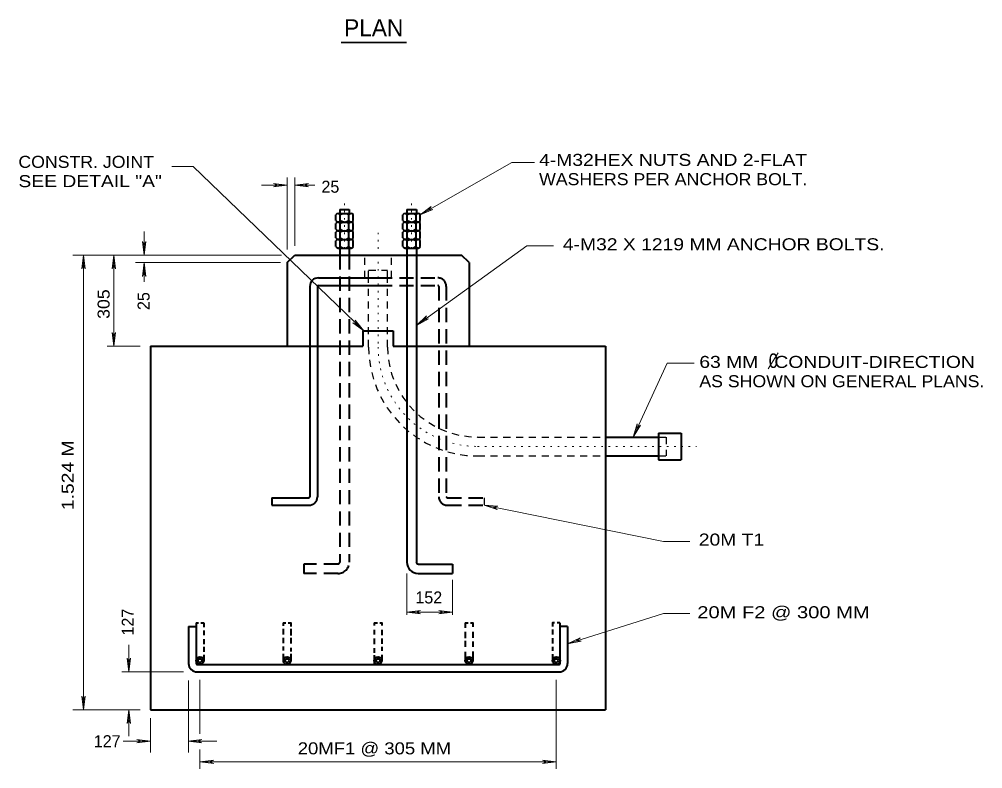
# Model space of a CAD drawing. Extents: x 312583 to 312854, y 144419 to 144597.
# Drawn here: x 312735.4 to 312796.3, y 144490 to 144537.4 of the extents above; entities that cross this region are included whole.
import ezdxf
from ezdxf.enums import TextEntityAlignment as Align

# ---------------------------------------------------------------- set-up
doc = ezdxf.new("R2010")
doc.units = 0
doc.header["$LTSCALE"] = 0.3
for name, pattern in [('DOTTED', [1.5, 0.3, -1.2]), ('MEDIUM_DASHED', [4.5, 3, -1.5]), ('SHORT_DASHED', [2.7, 1.5, -1.2])]:
    doc.linetypes.add(name, pattern=pattern)
doc.layers.add('1', color=7, linetype='Continuous', lineweight=40)
doc.layers.add('2', color=7, linetype='Continuous', lineweight=13)

msp = doc.modelspace()

# ---------------------------------------------------------------- linework, layer by layer
at = {"layer": '1', "linetype": 'DOTTED', "lineweight": 13}
for p, q in [((312755.9183, 144525.7646), (312755.9183, 144522.1076)), ((312760.158, 144525.7646), (312760.158, 144522.1076)), ((312758.0343, 144523.9169), (312758.0343, 144516.6873)), ((312764.3286, 144510.4006), (312778.167, 144510.4006))]:
    msp.add_line(p, q, dxfattribs=at)
at = {"layer": '1'}
for p, q in [((312755.374, 144524.6836), (312755.374, 144525.0516)), ((312755.512, 144525.1359), (312756.34, 144525.1359)), ((312755.6193, 144525.3736), (312756.2173, 144525.3736)), ((312755.6193, 144525.3736), (312755.6193, 144525.1359)), ((312755.65, 144524.6836), (312755.65, 144525.0516)), ((312756.1943, 144524.6836), (312756.1943, 144525.0516)), ((312756.2173, 144525.3736), (312756.2173, 144525.1359)), ((312756.4703, 144524.6836), (312756.4703, 144525.0516)), ((312759.606, 144524.6836), (312759.606, 144525.0516)), ((312759.744, 144525.1359), (312760.572, 144525.1359)), ((312759.859, 144525.3736), (312760.457, 144525.3736)), ((312759.859, 144525.3736), (312759.859, 144525.1359)), ((312759.882, 144524.6836), (312759.882, 144525.0516)), ((312760.434, 144524.6836), (312760.434, 144525.0516)), ((312760.457, 144525.3736), (312760.457, 144525.1359)), ((312760.7023, 144524.6836), (312760.7023, 144525.0516)), ((312755.374, 144524.1316), (312755.374, 144524.4996)), ((312755.512, 144524.5916), (312756.34, 144524.5916)), ((312755.512, 144524.5916), (312756.34, 144524.5916)), ((312755.65, 144524.1316), (312755.65, 144524.4996)), ((312756.1943, 144524.1316), (312756.1943, 144524.4996)), ((312756.4703, 144524.1316), (312756.4703, 144524.4996)), ((312759.606, 144524.1316), (312759.606, 144524.4996)), ((312759.744, 144524.5916), (312760.572, 144524.5916)), ((312759.744, 144524.5916), (312760.572, 144524.5916)), ((312759.882, 144524.1316), (312759.882, 144524.4996)), ((312760.434, 144524.1316), (312760.434, 144524.4996)), ((312760.7023, 144524.1316), (312760.7023, 144524.4996)), ((312755.374, 144523.5873), (312755.374, 144523.9553)), ((312755.512, 144524.0396), (312756.34, 144524.0396)), ((312755.65, 144523.5873), (312755.65, 144523.9553)), ((312756.1943, 144523.5873), (312756.1943, 144523.9553)), ((312756.4703, 144523.5873), (312756.4703, 144523.9553)), ((312759.606, 144523.5873), (312759.606, 144523.9553)), ((312759.744, 144524.0396), (312760.572, 144524.0396)), ((312759.882, 144523.5873), (312759.882, 144523.9553)), ((312760.434, 144523.5873), (312760.434, 144523.9553)), ((312760.7023, 144523.5873), (312760.7023, 144523.9553)), ((312755.374, 144523.0353), (312755.374, 144523.4033)), ((312755.512, 144523.4953), (312756.34, 144523.4953)), ((312755.65, 144523.0353), (312755.65, 144523.4033)), ((312756.1943, 144523.0353), (312756.1943, 144523.4033)), ((312756.4703, 144523.0353), (312756.4703, 144523.4033)), ((312759.606, 144523.0353), (312759.606, 144523.4033)), ((312759.744, 144523.4953), (312760.572, 144523.4953)), ((312759.882, 144523.0353), (312759.882, 144523.4033)), ((312760.434, 144523.0353), (312760.434, 144523.4033)), ((312760.7023, 144523.0353), (312760.7023, 144523.4033)), ((312755.512, 144522.9433), (312756.34, 144522.9433)), ((312755.6193, 144522.9433), (312755.6193, 144522.4986)), ((312756.2173, 144522.9433), (312756.2173, 144522.4986)), ((312759.744, 144522.9433), (312760.572, 144522.9433)), ((312759.859, 144522.9433), (312759.859, 144503.0943)), ((312760.457, 144522.9433), (312760.457, 144503.0943)), ((312752.2843, 144522.0233), (312752.7673, 144522.4986)), ((312752.2843, 144522.0233), (312752.2843, 144516.7486)), ((312752.7673, 144522.4986), (312763.309, 144522.4986)), ((312763.7843, 144522.0233), (312763.309, 144522.4986)), ((312763.7843, 144522.0233), (312763.7843, 144516.7486)), ((312754.2623, 144521.0649), (312758.0343, 144521.0649)), ((312753.7256, 144520.5206), (312753.7256, 144507.2266)), ((312754.201, 144520.5206), (312754.201, 144507.2266)), ((312754.2623, 144520.5819), (312758.0343, 144520.5819)), ((312757.076, 144517.7069), (312758.9926, 144517.7069)), ((312757.076, 144517.7069), (312757.076, 144516.7486)), ((312758.9926, 144517.7069), (312758.9926, 144516.7486)), ((312743.6593, 144516.7486), (312743.6593, 144493.7486)), ((312743.6593, 144516.7486), (312757.076, 144516.7486)), ((312758.9926, 144516.7486), (312772.4093, 144516.7486)), ((312772.4093, 144516.7486), (312772.4093, 144493.7486)), ((312772.4093, 144510.9986), (312775.7673, 144510.9986)), ((312775.7673, 144511.2363), (312775.7673, 144509.5649)), ((312775.7673, 144511.2363), (312777.201, 144511.2363)), ((312777.201, 144511.2363), (312777.201, 144509.5649)), ((312772.4093, 144509.8026), (312775.7673, 144509.8026)), ((312775.7673, 144509.5649), (312777.201, 144509.5649)), ((312751.326, 144507.1653), (312753.6643, 144507.1653)), ((312751.326, 144507.1653), (312751.326, 144506.6899)), ((312751.326, 144506.6899), (312753.6643, 144506.6899)), ((312760.572, 144502.9716), (312762.734, 144502.9716)), ((312762.734, 144502.9716), (312762.734, 144502.3736)), ((312760.572, 144502.3736), (312762.734, 144502.3736)), ((312746.059, 144499.0233), (312746.059, 144496.6849)), ((312746.059, 144499.0233), (312746.5343, 144499.0233)), ((312746.5343, 144499.2609), (312746.5343, 144496.6849)), ((312746.5343, 144499.2609), (312746.6953, 144499.2609)), ((312746.841, 144499.2609), (312747.0173, 144499.2609)), ((312747.0173, 144499.2609), (312747.0173, 144498.9696)), ((312752.0466, 144499.2609), (312752.0466, 144499.0539)), ((312752.0466, 144499.2609), (312752.2, 144499.2609)), ((312752.0466, 144498.8699), (312752.0466, 144498.5096)), ((312752.5296, 144498.8699), (312752.5296, 144498.4483)), ((312757.7966, 144499.2609), (312757.7966, 144499.0923)), ((312757.7966, 144499.2609), (312757.996, 144499.2609)), ((312757.7966, 144498.8009), (312757.7966, 144498.5096)), ((312758.2796, 144498.8009), (312758.2796, 144498.4713)), ((312763.5466, 144499.2609), (312763.723, 144499.2609)), ((312763.5466, 144499.2609), (312763.5466, 144498.9313)), ((312769.059, 144498.8239), (312769.059, 144498.5096)), ((312769.5343, 144499.2609), (312769.3503, 144499.2609)), ((312769.5343, 144499.2609), (312769.5343, 144496.6849)), ((312770.0173, 144499.0233), (312769.5343, 144499.0233)), ((312770.0173, 144499.0233), (312770.0173, 144496.6849)), ((312747.0173, 144498.7626), (312747.0173, 144498.4713)), ((312747.0173, 144498.2259), (312747.0173, 144497.9116)), ((312752.0466, 144498.3026), (312752.0466, 144497.9729)), ((312752.5296, 144498.3026), (312752.5296, 144497.9499)), ((312757.7966, 144498.2643), (312757.7966, 144497.9116)), ((312758.2796, 144498.2643), (312758.2796, 144497.9346)), ((312763.5466, 144498.6783), (312763.5466, 144498.2873)), ((312764.0296, 144498.6783), (312764.0296, 144498.3026)), ((312769.059, 144498.2873), (312769.059, 144497.9499)), ((312747.0173, 144497.7276), (312747.0173, 144497.4133)), ((312752.0466, 144497.7659), (312752.0466, 144497.5129)), ((312752.5296, 144497.6816), (312752.5296, 144497.4363)), ((312757.7966, 144497.6586), (312757.7966, 144497.3519)), ((312758.2796, 144497.7276), (312758.2796, 144497.4746)), ((312763.5466, 144498.1186), (312763.5466, 144497.7429)), ((312764.0296, 144498.0803), (312764.0296, 144497.7276)), ((312769.059, 144497.7429), (312769.059, 144497.4746)), ((312747.0173, 144497.2293), (312747.0173, 144496.8613)), ((312752.0466, 144497.2906), (312752.0466, 144496.8613)), ((312752.5296, 144497.2906), (312752.5296, 144496.8613)), ((312757.7966, 144497.2063), (312757.7966, 144496.6849)), ((312758.2796, 144497.2293), (312758.2796, 144496.8613)), ((312763.5466, 144497.4133), (312763.5466, 144496.8613)), ((312764.0296, 144497.4363), (312764.0296, 144496.8613)), ((312769.059, 144497.2676), (312769.059, 144496.8613)), ((312746.5956, 144496.6236), (312769.4806, 144496.6236)), ((312746.5956, 144496.1483), (312769.4806, 144496.1483)), ((312743.6593, 144493.7486), (312772.4093, 144493.7486))]:
    msp.add_line(p, q, dxfattribs=at)
at = {"layer": '1', "linetype": 'MEDIUM_DASHED'}
for p, q in [((312755.6193, 144522.4986), (312755.6193, 144503.0943)), ((312756.2173, 144522.4986), (312756.2173, 144503.0943)), ((312758.0343, 144521.0649), (312761.814, 144521.0649)), ((312758.0343, 144520.5819), (312761.814, 144520.5819)), ((312761.8676, 144520.5206), (312761.8676, 144507.2266)), ((312762.3506, 144520.5206), (312762.3506, 144507.2266)), ((312762.412, 144507.1653), (312764.7426, 144507.1653)), ((312762.412, 144506.6899), (312764.7426, 144506.6899)), ((312753.3423, 144502.9716), (312753.3423, 144502.3736)), ((312755.5043, 144502.9716), (312753.3423, 144502.9716)), ((312755.5043, 144502.3736), (312753.3423, 144502.3736))]:
    msp.add_line(p, q, dxfattribs=at)
at = {"layer": '1', "linetype": 'SHORT_DASHED', "lineweight": 25}
for p, q in [((312757.1986, 144521.0649), (312757.1986, 144522.4986)), ((312758.8776, 144521.0649), (312758.8776, 144522.4986)), ((312757.4363, 144521.5403), (312758.64, 144521.5403)), ((312757.4363, 144521.0649), (312757.4363, 144521.5403)), ((312758.64, 144521.0649), (312758.64, 144521.5403)), ((312757.4363, 144516.6873), (312757.4363, 144521.0649)), ((312758.64, 144516.6873), (312758.64, 144521.0649)), ((312764.3286, 144510.9986), (312772.4093, 144510.9986)), ((312775.7673, 144510.9986), (312776.2426, 144510.9986)), ((312776.2426, 144510.9986), (312776.2426, 144509.8026)), ((312764.3286, 144509.8026), (312772.4093, 144509.8026)), ((312775.7673, 144509.8026), (312776.2426, 144509.8026)), ((312764.7426, 144507.1653), (312764.7426, 144506.6899))]:
    msp.add_line(p, q, dxfattribs=at)
at = {"layer": '1'}
for points in [[(312752.3456, 144499.2609), (312752.5296, 144499.2609), (312752.5296, 144499.0309)], [(312758.157, 144499.2609), (312758.2796, 144499.2609), (312758.2796, 144499.0769)], [(312763.8686, 144499.2609), (312764.0296, 144499.2609), (312764.0296, 144498.9926)], [(312769.1893, 144499.2609), (312769.059, 144499.2609), (312769.059, 144499.0309)]]:
    msp.add_lwpolyline(points, dxfattribs=at)
for centre, radius in [((312746.7772, 144496.8646), 0.2396), ((312746.7772, 144496.8646), 0.1198), ((312752.2877, 144496.8646), 0.2396), ((312752.2877, 144496.8646), 0.1198), ((312758.0377, 144496.8646), 0.2396), ((312758.0377, 144496.8646), 0.1198), ((312763.7877, 144496.8646), 0.2396), ((312763.7877, 144496.8646), 0.1198), ((312769.2981, 144496.8646), 0.2396), ((312769.2981, 144496.8646), 0.1198)]:
    msp.add_circle(centre, radius, dxfattribs=at)
for centre, radius, start, end in [((312755.5095, 144524.9893), 0.1495, 23.18435, 156.81565), ((312755.9211, 144524.6789), 0.4599, 53.40512, 126.59488), ((312756.332, 144524.9904), 0.1484, 22.90211, 157.09789), ((312759.7443, 144524.9893), 0.1495, 23.18435, 156.81565), ((312760.156, 144524.6789), 0.4599, 53.40512, 126.59488), ((312760.5669, 144524.9904), 0.1484, 22.90211, 157.09789), ((312755.5095, 144524.7401), 0.1495, 203.18435, 336.81565), ((312755.5095, 144524.4411), 0.1495, 23.18435, 156.81565), ((312755.9211, 144525.0505), 0.4599, 233.40512, 306.59488), ((312755.9211, 144524.1307), 0.4599, 53.40512, 126.59488), ((312756.332, 144524.739), 0.1484, 202.90211, 337.09789), ((312756.332, 144524.4422), 0.1484, 22.90211, 157.09789), ((312759.7443, 144524.7401), 0.1495, 203.18435, 336.81565), ((312759.7443, 144524.4411), 0.1495, 23.18435, 156.81565), ((312760.156, 144525.0505), 0.4599, 233.40512, 306.59488), ((312760.156, 144524.1307), 0.4599, 53.40512, 126.59488), ((312760.5669, 144524.739), 0.1484, 202.90211, 337.09789), ((312760.5669, 144524.4422), 0.1484, 22.90211, 157.09789), ((312755.5095, 144524.1919), 0.1495, 203.18435, 336.81565), ((312755.5095, 144523.893), 0.1495, 23.18435, 156.81565), ((312755.9211, 144524.5023), 0.4599, 233.40512, 306.59488), ((312755.9211, 144523.5826), 0.4599, 53.40512, 126.59488), ((312756.332, 144524.1908), 0.1484, 202.90211, 337.09789), ((312756.332, 144523.8941), 0.1484, 22.90211, 157.09789), ((312759.7443, 144524.1919), 0.1495, 203.18435, 336.81565), ((312759.7443, 144523.893), 0.1495, 23.18435, 156.81565), ((312760.156, 144524.5023), 0.4599, 233.40512, 306.59488), ((312760.156, 144523.5826), 0.4599, 53.40512, 126.59488), ((312760.5669, 144524.1908), 0.1484, 202.90211, 337.09789), ((312760.5669, 144523.8941), 0.1484, 22.90211, 157.09789), ((312755.5095, 144523.6438), 0.1495, 203.18435, 336.81565), ((312755.5095, 144523.3448), 0.1495, 23.18435, 156.81565), ((312755.9211, 144523.9542), 0.4599, 233.40512, 306.59488), ((312755.9211, 144523.0344), 0.4599, 53.40512, 126.59488), ((312756.332, 144523.6427), 0.1484, 202.90211, 337.09789), ((312756.332, 144523.3459), 0.1484, 22.90211, 157.09789), ((312759.7443, 144523.6438), 0.1495, 203.18435, 336.81565), ((312759.7443, 144523.3448), 0.1495, 23.18435, 156.81565), ((312760.156, 144523.9542), 0.4599, 233.40512, 306.59488), ((312760.156, 144523.0344), 0.4599, 53.40512, 126.59488), ((312760.5669, 144523.6427), 0.1484, 202.90211, 337.09789), ((312760.5669, 144523.3459), 0.1484, 22.90211, 157.09789), ((312755.5095, 144523.0956), 0.1495, 203.18435, 336.81565), ((312755.9211, 144523.406), 0.4599, 233.40512, 306.59488), ((312756.332, 144523.0945), 0.1484, 202.90211, 337.09789), ((312759.7443, 144523.0956), 0.1495, 203.18435, 336.81565), ((312760.156, 144523.406), 0.4599, 233.40512, 306.59488), ((312760.5669, 144523.0945), 0.1484, 202.90211, 337.09789), ((312754.2642, 144520.5235), 0.5391, 90, 180), ((312754.2642, 144520.5235), 0.0599, 90, 180), ((312753.6653, 144507.2266), 0.5391, 270, 0), ((312753.6653, 144507.2266), 0.0599, 270, 0), ((312760.5744, 144503.0943), 0.7188, 180, 270), ((312760.5744, 144503.0943), 0.1198, 180, 270), ((312746.5976, 144496.6849), 0.5391, 180, 270), ((312746.5976, 144496.6849), 0.0599, 180, 270), ((312769.4778, 144496.6849), 0.5391, 270, 0), ((312769.4778, 144496.6849), 0.0599, 270, 0)]:
    msp.add_arc(centre, radius, start, end, dxfattribs=at)
at = {"layer": '1', "linetype": 'MEDIUM_DASHED'}
for centre, radius, start, end in [((312761.8111, 144520.5235), 0.5391, 0, 90), ((312761.8111, 144520.5235), 0.0599, 0, 90), ((312762.4101, 144507.2266), 0.5391, 180, 270), ((312762.4101, 144507.2266), 0.0599, 180, 270), ((312755.5009, 144503.0943), 0.7188, 270, 0), ((312755.5009, 144503.0943), 0.1198, 270, 0)]:
    msp.add_arc(centre, radius, start, end, dxfattribs=at)
at = {"layer": '1', "linetype": 'SHORT_DASHED', "lineweight": 25}
for radius in [6.888, 5.6901]:
    msp.add_arc((312764.3267, 144516.6901), radius, 180, 270, dxfattribs=at)
at = {"layer": '1', "linetype": 'DOTTED', "lineweight": 13}
msp.add_arc((312764.3267, 144516.6901), 6.2891, 180, 270, dxfattribs=at)
at = {"layer": '2', "lineweight": 35}
msp.add_line((312755.7068, 144535.9349), (312759.8405, 144535.9349), dxfattribs=at)
at = {"layer": '2'}
for p, q in [((312745.001, 144528.0953), (312746.3426, 144528.0953)), ((312757.145, 144517.7069), (312746.3426, 144528.0953)), ((312760.7023, 144525.0516), (312766.4906, 144528.3636)), ((312766.4906, 144528.3636), (312767.9243, 144528.3636)), ((312752.2843, 144522.8513), (312752.2843, 144527.4053)), ((312752.7673, 144523.0889), (312752.7673, 144527.4053)), ((312752.2843, 144526.9223), (312750.6743, 144526.9223)), ((312751.418, 144527.0296), (312751.694, 144526.9223)), ((312752.2843, 144526.9223), (312751.418, 144527.0296)), ((312751.418, 144526.8149), (312751.694, 144526.9223)), ((312752.2843, 144526.9223), (312751.418, 144526.8149)), ((312752.7673, 144526.9223), (312753.6336, 144527.0296)), ((312754.0323, 144526.9223), (312752.7673, 144526.9223)), ((312752.7673, 144526.9223), (312753.6336, 144526.8149)), ((312753.6336, 144527.0296), (312753.3576, 144526.9223)), ((312753.6336, 144526.8149), (312753.3576, 144526.9223)), ((312760.7023, 144525.0516), (312761.4, 144525.5729)), ((312761.4, 144525.5729), (312761.216, 144525.3429)), ((312760.7023, 144525.0516), (312761.5073, 144525.3889)), ((312761.5073, 144525.3889), (312761.216, 144525.3429)), ((312743.2453, 144522.4986), (312743.2453, 144523.9859)), ((312743.138, 144523.3649), (312743.2453, 144523.0889)), ((312743.2453, 144522.4986), (312743.138, 144523.3649)), ((312743.3526, 144523.3649), (312743.2453, 144523.0889)), ((312743.2453, 144522.4986), (312743.3526, 144523.3649)), ((312760.457, 144518.0596), (312767.449, 144523.0889)), ((312767.449, 144523.0889), (312769.1203, 144523.0889)), ((312751.924, 144522.4986), (312738.7526, 144522.4986)), ((312739.412, 144522.4986), (312739.3046, 144521.6323)), ((312739.412, 144493.7486), (312739.412, 144522.4986)), ((312739.412, 144522.4986), (312739.5193, 144521.6323)), ((312741.3286, 144522.4986), (312741.2213, 144521.6323)), ((312741.3286, 144516.7486), (312741.3286, 144522.4986)), ((312741.3286, 144522.4986), (312741.436, 144521.6323)), ((312751.8703, 144522.0233), (312742.7086, 144522.0233)), ((312743.2453, 144522.0233), (312743.138, 144521.1569)), ((312743.2453, 144520.8043), (312743.2453, 144522.0233)), ((312743.2453, 144522.0233), (312743.3526, 144521.1569)), ((312739.3046, 144521.6323), (312739.412, 144521.9083)), ((312739.5193, 144521.6323), (312739.412, 144521.9083)), ((312741.2213, 144521.6323), (312741.3286, 144521.9083)), ((312741.436, 144521.6323), (312741.3286, 144521.9083)), ((312743.138, 144521.1569), (312743.2453, 144521.4329)), ((312743.3526, 144521.1569), (312743.2453, 144521.4329)), ((312756.593, 144518.3893), (312756.7156, 144518.1209)), ((312757.145, 144517.7069), (312756.593, 144518.3893)), ((312760.457, 144518.0596), (312761.0933, 144518.6576)), ((312760.457, 144518.0596), (312761.2236, 144518.4813)), ((312761.0933, 144518.6576), (312760.9323, 144518.4046)), ((312761.2236, 144518.4813), (312760.9323, 144518.4046)), ((312756.4473, 144518.2283), (312756.7156, 144518.1209)), ((312757.145, 144517.7069), (312756.4473, 144518.2283)), ((312741.2213, 144517.6149), (312741.3286, 144517.3389)), ((312741.3286, 144516.7486), (312741.2213, 144517.6149)), ((312741.436, 144517.6149), (312741.3286, 144517.3389)), ((312741.3286, 144516.7486), (312741.436, 144517.6149)), ((312743.0076, 144516.7486), (312740.907, 144516.7486)), ((312782.6918, 144515.3108), (312783.3282, 144516.3304)), ((312774.1573, 144510.9986), (312776.3116, 144515.6676)), ((312776.3116, 144515.6676), (312778.006, 144515.6676)), ((312774.1573, 144510.9986), (312774.418, 144511.8343)), ((312774.1573, 144510.9986), (312774.6173, 144511.7423)), ((312774.418, 144511.8343), (312774.4026, 144511.5353)), ((312774.6173, 144511.7423), (312774.4026, 144511.5353)), ((312764.7426, 144506.6899), (312776.074, 144504.4053)), ((312764.7426, 144506.6899), (312765.5706, 144506.4139)), ((312764.7426, 144506.6899), (312765.6166, 144506.6209)), ((312765.6166, 144506.6209), (312765.3253, 144506.5749)), ((312765.5706, 144506.4139), (312765.3253, 144506.5749)), ((312776.074, 144504.4053), (312777.7453, 144504.4053)), ((312759.859, 144502.3659), (312759.859, 144499.7593)), ((312762.734, 144501.9673), (312762.734, 144499.7593)), ((312759.859, 144499.9356), (312760.7253, 144500.0429)), ((312760.7253, 144500.0429), (312760.4493, 144499.9356)), ((312761.8676, 144500.0429), (312762.1436, 144499.9356)), ((312762.734, 144499.9356), (312761.8676, 144500.0429)), ((312759.859, 144499.9356), (312762.734, 144499.9356)), ((312759.859, 144499.9356), (312760.7253, 144499.8283)), ((312760.7253, 144499.8283), (312760.4493, 144499.9356)), ((312761.8676, 144499.8283), (312762.1436, 144499.9356)), ((312762.734, 144499.9356), (312761.8676, 144499.8283)), ((312770.0173, 144497.9346), (312776.074, 144499.8513)), ((312776.074, 144499.8513), (312777.7453, 144499.8513)), ((312770.0173, 144497.9346), (312770.807, 144498.3026)), ((312770.807, 144498.3026), (312770.577, 144498.1109)), ((312742.287, 144496.1483), (312742.287, 144497.8579)), ((312770.0173, 144497.9346), (312770.876, 144498.0956)), ((312770.876, 144498.0956), (312770.577, 144498.1109)), ((312742.1796, 144497.0146), (312742.287, 144496.7386)), ((312742.287, 144496.1483), (312742.1796, 144497.0146)), ((312742.3943, 144497.0146), (312742.287, 144496.7386)), ((312742.287, 144496.1483), (312742.3943, 144497.0146)), ((312745.7293, 144496.1483), (312741.85, 144496.1483)), ((312746.059, 144495.6116), (312746.059, 144491.0576)), ((312746.7796, 144495.6499), (312746.7796, 144492.2306)), ((312769.2966, 144495.6499), (312769.2966, 144490.0303)), ((312739.3046, 144494.6149), (312739.412, 144494.3389)), ((312739.412, 144493.7486), (312739.3046, 144494.6149)), ((312739.5193, 144494.6149), (312739.412, 144494.3389)), ((312739.412, 144493.7486), (312739.5193, 144494.6149)), ((312743.0076, 144493.7486), (312738.7526, 144493.7486)), ((312742.287, 144493.7486), (312742.1796, 144492.8823)), ((312742.287, 144492.0926), (312742.287, 144493.7486)), ((312742.287, 144493.7486), (312742.3943, 144492.8823)), ((312742.1796, 144492.8823), (312742.287, 144493.1583)), ((312742.3943, 144492.8823), (312742.287, 144493.1583)), ((312743.6593, 144493.2273), (312743.6593, 144491.0576)), ((312743.6593, 144491.7706), (312741.919, 144491.7706)), ((312742.793, 144491.8779), (312743.069, 144491.7706)), ((312743.6593, 144491.7706), (312742.793, 144491.8779)), ((312742.793, 144491.6633), (312743.069, 144491.7706)), ((312743.6593, 144491.7706), (312742.793, 144491.6633)), ((312746.036, 144491.7706), (312746.9023, 144491.8779)), ((312747.8376, 144491.7706), (312746.036, 144491.7706)), ((312746.036, 144491.7706), (312746.9023, 144491.6633)), ((312746.9023, 144491.8779), (312746.6263, 144491.7706)), ((312746.9023, 144491.6633), (312746.6263, 144491.7706)), ((312746.7796, 144491.2416), (312746.7796, 144490.0303)), ((312746.7796, 144490.4673), (312747.646, 144490.5746)), ((312769.2966, 144490.4673), (312746.7796, 144490.4673)), ((312746.7796, 144490.4673), (312747.646, 144490.3599)), ((312747.646, 144490.5746), (312747.37, 144490.4673)), ((312747.646, 144490.3599), (312747.37, 144490.4673)), ((312768.4303, 144490.5746), (312768.7063, 144490.4673)), ((312769.2966, 144490.4673), (312768.4303, 144490.5746)), ((312768.4303, 144490.3599), (312768.7063, 144490.4673)), ((312769.2966, 144490.4673), (312768.4303, 144490.3599))]:
    msp.add_line(p, q, dxfattribs=at)

# ---------------------------------------------------------------- texts
msp.add_text('PLAN', height=1.07, dxfattribs=at).set_placement((312757.7614, 144536.338), align=Align.CENTER)
for s, width, p in [('CONSTR. JOINT', 1.1, (312735.3014, 144528.0146)), ('4-M32HEX NUTS AND 2-FLAT', 1.2, (312768.2156, 144528.1403)), ('SEE DETAIL "A"', 1.2, (312735.3014, 144526.7946)), ('WASHERS PER ANCHOR BOLT.', 1.1, (312768.2156, 144526.9203)), ('4-M32 X 1219 MM ANCHOR BOLTS.', 1.2, (312769.7149, 144522.8036)), ('63 MM   CONDUIT-DIRECTION', 1.2, (312778.3433, 144515.3676)), ('AS SHOWN ON GENERAL PLANS.', 1.1, (312778.3433, 144514.1476)), ('20M T1', 1.2, (312778.3093, 144504.1352)), ('20M F2 @ 300 MM', 1.25, (312778.2151, 144499.5429)), ('20MF1 @ 305 MM', 1.15, (312752.9581, 144490.9391))]:
    msp.add_text(s, height=0.76, dxfattribs=dict(at, width=width)).set_placement(p)
for s, p in [('25', (312754.4561, 144526.443)), ('152', (312760.3931, 144500.4776)), ('127', (312740.0668, 144491.3909))]:
    msp.add_text(s, height=0.76, dxfattribs=at).set_placement(p)
for s, width, p in [('305', 1.1, (312741.068, 144518.4688)), ('1.524 M', 1.2, (312738.8012, 144506.3778))]:
    msp.add_text(s, height=0.76, rotation=90, dxfattribs=dict(at, width=width)).set_placement(p)
for s, p in [('25', (312743.5931, 144519.0263)), ('127', (312742.5959, 144498.4493))]:
    msp.add_text(s, height=0.76, rotation=90, dxfattribs=at).set_placement(p)
at = {"layer": '2', "width": 0.85}
msp.add_text('0', height=0.92, dxfattribs=at).set_placement((312783.0215, 144515.3644), align=Align.CENTER)

doc.saveas('drawing.dxf')
